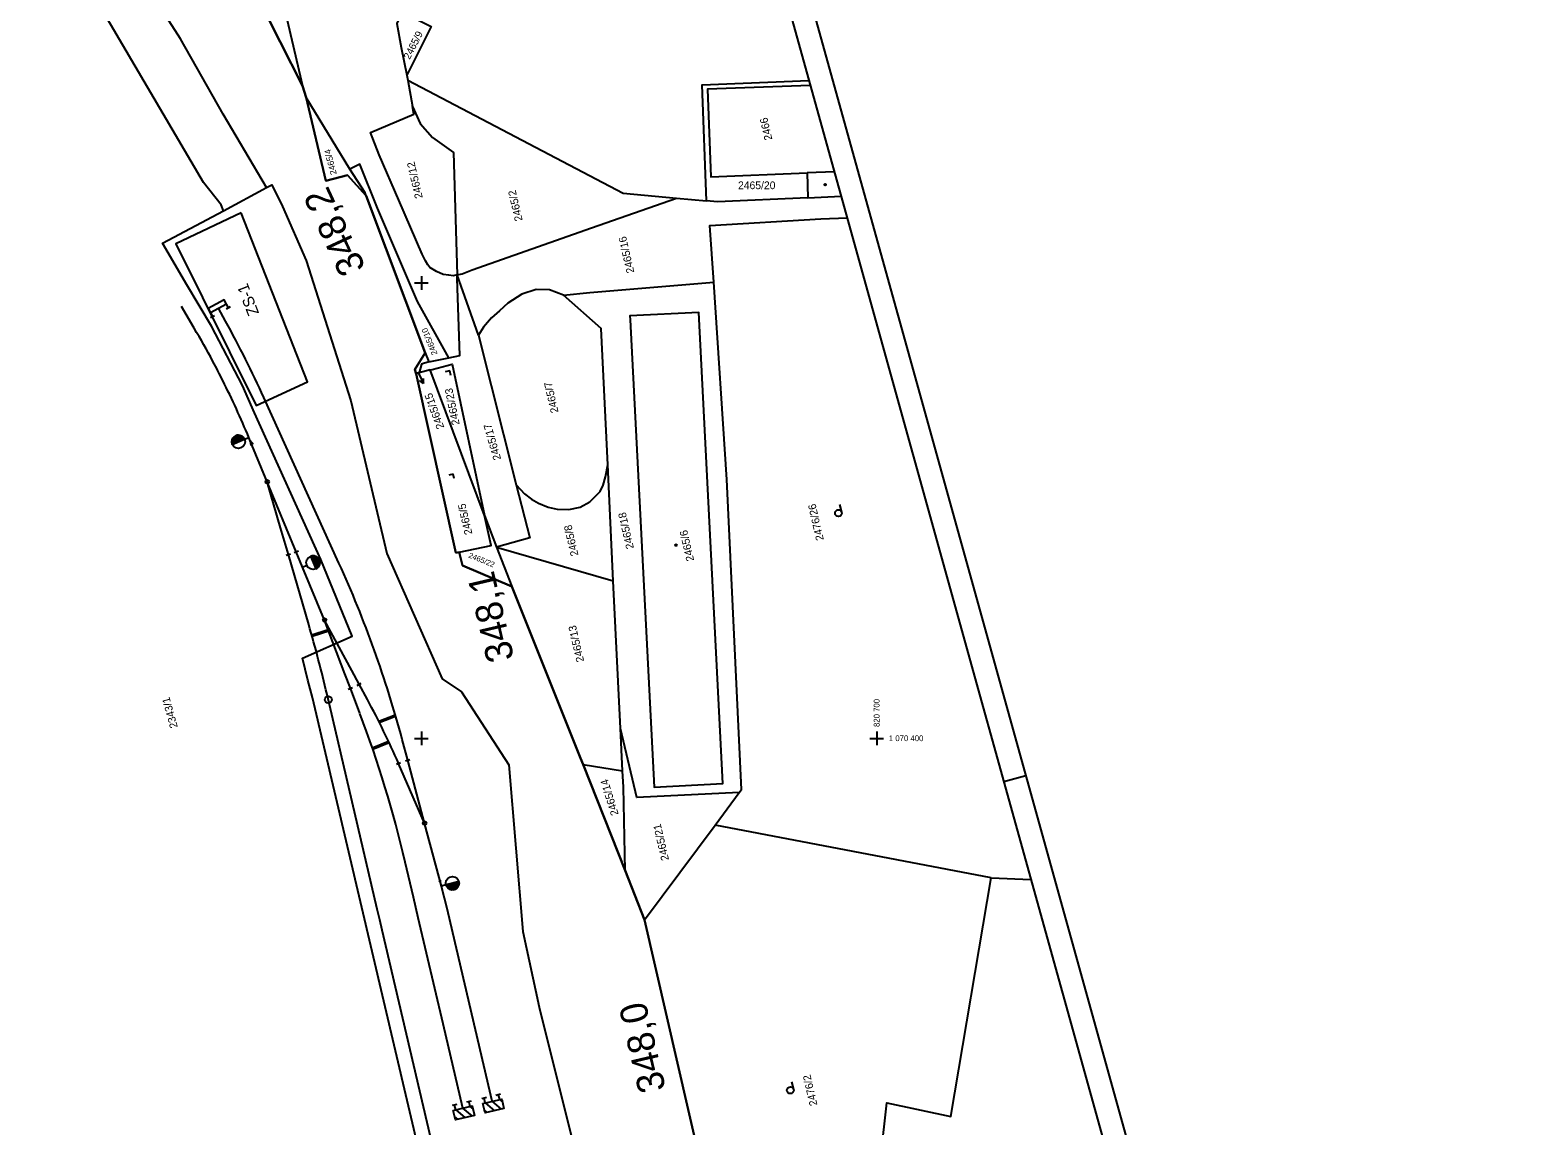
# Model space of a CAD drawing. Extents: x -821122 to -820555, y -1070892 to -1069801.
# Drawn here: x -820885.9 to -820554.8, y -1070485 to -1070244.5 of the extents above; entities that cross this region are included whole.
import ezdxf

# ---------------------------------------------------------------- set-up
doc = ezdxf.new("R2010")
doc.units = 0
for name, color, linetype in [('Hranice drážního pozemku', 7, 'Continuous'), ('Hranice parcel', 7, 'Continuous'), ('Katastrální hranice', 7, 'Continuous'), ('Osa staničení koleje', 7, 'Continuous'), ('Parcelní čísla', 7, 'Continuous'), ('Pop  PČ popisy', 7, 'Continuous'), ('Ram', 7, 'Continuous'), ('Sttaniceni a namezniky', 7, 'Continuous'), ('Vnitřní kresba', 7, 'Continuous'), ('Vrstva 61', 7, 'Continuous'), ('Vrstva 63', 7, 'Continuous'), ('Značky budov', 7, 'Continuous'), ('Značky kultur', 7, 'Continuous')]:
    doc.layers.add(name, color=color, linetype=linetype)

msp = doc.modelspace()

# ---------------------------------------------------------------- linework, layer by layer
at = {"layer": 'Hranice drážního pozemku'}
for p, q in [((-820835.88, -1070237.32), (-820826.1, -1070256.7)), ((-820826.1, -1070256.7), (-820825.3, -1070259.25)), ((-820812.1, -1070280.9), (-820812.1, -1070280.9)), ((-820812.1, -1070280.9), (-820799.14, -1070315.36)), ((-820801.15, -1070319.91), (-820792.39, -1070359.23)), ((-820792.39, -1070359.23), (-820791.67, -1070359.08)), ((-820780.16, -1070366.62), (-820765.05, -1070404.29)), ((-820765.05, -1070404.29), (-820764.48, -1070405.73)), ((-820764.48, -1070405.73), (-820755.27, -1070429)), ((-820755.27, -1070429), (-820751, -1070439.83)), ((-820751, -1070439.83), (-820721.42, -1070568.42))]:
    msp.add_line(p, q, dxfattribs=at)
for points in [[(-820825.3, -1070259.25), (-820821, -1070277.6), (-820816.2, -1070276.3), (-820812.1, -1070280.9)], [(-820799.14, -1070315.36), (-820801.45, -1070319), (-820801.15, -1070319.91)], [(-820791.67, -1070359.08), (-820790.95, -1070362.05), (-820780.16, -1070366.62)]]:
    msp.add_lwpolyline(points, dxfattribs=at)
at = {"layer": 'Hranice parcel'}
for p, q in [((-820803.2, -1070254.4), (-820803, -1070255.5)), ((-820803, -1070255.5), (-820801.94, -1070261.25)), ((-820815.71, -1070274.99), (-820825.3, -1070259.25)), ((-820744, -1070281.37), (-820737.36, -1070281.98)), ((-820787.47, -1070311.48), (-820792.13, -1070298.22)), ((-820787.47, -1070311.48), (-820779.15, -1070344.32)), ((-820799.14, -1070315.36), (-820798.35, -1070317.32)), ((-820798.35, -1070317.32), (-820793.99, -1070316.42)), ((-820800.46, -1070319.73), (-820801.15, -1070319.91)), ((-820798.04, -1070319.1), (-820800.46, -1070319.73)), ((-820786.11, -1070351.02), (-820798.04, -1070319.1)), ((-820757.86, -1070365.37), (-820759.03, -1070339.93)), ((-820786.11, -1070351.02), (-820783.5, -1070358)), ((-820783.5, -1070358), (-820757.86, -1070365.37)), ((-820783.5, -1070358), (-820780.16, -1070366.62)), ((-820756.26, -1070397.81), (-820757.86, -1070365.37)), ((-820755.8, -1070407.09), (-820756.26, -1070397.81)), ((-820764.48, -1070405.73), (-820755.8, -1070407.09)), ((-820735.51, -1070419.02), (-820730.21, -1070411.89)), ((-820751, -1070439.83), (-820735.51, -1070419.02)), ((-820674.9, -1070430.61), (-820735.51, -1070419.02)), ((-820674.9, -1070430.61), (-820666.15, -1070430.93))]:
    msp.add_line(p, q, dxfattribs=at)
for points in [[(-820830.93, -1070230.58), (-820830.77, -1070236.59), (-820826.1, -1070256.7)], [(-820804.2, -1070240.46), (-820805.38, -1070243.04), (-820804.45, -1070248.28), (-820803.2, -1070254.4)], [(-820804.2, -1070240.46), (-820797.83, -1070243.67), (-820803.2, -1070254.4)], [(-820803, -1070255.5), (-820755.71, -1070280.3), (-820744, -1070281.37)], [(-820737.36, -1070281.98), (-820738.31, -1070256.5), (-820714.88, -1070255.56)], [(-820714.59, -1070256.61), (-820737.16, -1070257.48), (-820736.4, -1070276.66), (-820715.25, -1070275.85), (-820715.14, -1070281.29)], [(-820792.13, -1070298.22), (-820793, -1070298.4), (-820793.95, -1070298.3), (-820795.2, -1070298.1), (-820796.7, -1070297.5), (-820798.1, -1070296.6), (-820798.6, -1070296), (-820799.1, -1070295.1), (-820799.82, -1070293.66), (-820804.97, -1070281.8), (-820809.25, -1070271.85), (-820811.2, -1070266.98), (-820801.63, -1070262.92), (-820801.94, -1070261.25)], [(-820801.94, -1070261.25), (-820800.23, -1070264.95), (-820797.52, -1070268.04), (-820792.96, -1070271.33), (-820792.13, -1070298.22)], [(-820793.99, -1070316.42), (-820800.87, -1070304.08), (-820809.66, -1070283.54), (-820813.53, -1070273.91), (-820815.71, -1070274.99)], [(-820812.1, -1070280.9), (-820812.3, -1070280.2), (-820815.71, -1070274.99)], [(-820792.13, -1070298.22), (-820791, -1070298), (-820788.84, -1070297.13), (-820762.63, -1070287.92), (-820744, -1070281.37)], [(-820715.14, -1070281.29), (-820735, -1070282.2), (-820737.36, -1070281.98)], [(-820715.14, -1070281.29), (-820707.82, -1070280.96)], [(-820735.8, -1070299.79), (-820736.63, -1070287.37), (-820712.28, -1070285.91), (-820706.49, -1070285.73)], [(-820793.99, -1070316.42), (-820791.57, -1070315.92), (-820792.1, -1070299.04), (-820792.13, -1070298.22)], [(-820768.79, -1070302.68), (-820771.86, -1070301.49), (-820774.82, -1070301.43), (-820777.93, -1070302.46), (-820780.99, -1070304.44), (-820782.84, -1070306.1), (-820784.56, -1070307.68), (-820786.32, -1070309.72), (-820787.47, -1070311.48)], [(-820768.79, -1070302.68), (-820763, -1070302.1), (-820735.8, -1070299.79)], [(-820730.21, -1070411.89), (-820729.73, -1070411.24), (-820732.91, -1070343.18), (-820735.8, -1070299.79)], [(-820759.03, -1070339.93), (-820760.52, -1070309.99), (-820768.79, -1070302.68)], [(-820754.18, -1070308.11), (-820748.91, -1070410.67), (-820733.78, -1070409.91), (-820739.09, -1070306.45), (-820754.22, -1070307.24), (-820754.18, -1070308.11)], [(-820798.35, -1070317.32), (-820799.93, -1070317.83), (-820800.46, -1070319.73)], [(-820798.04, -1070319.1), (-820797.62, -1070318.99), (-820793.2, -1070317.84), (-820786.11, -1070351.02)], [(-820779.15, -1070344.32), (-820777.33, -1070346.31), (-820775.83, -1070347.45), (-820774.3, -1070348.31), (-820772.13, -1070349.23), (-820770.14, -1070349.67), (-820767.58, -1070349.73), (-820765.16, -1070349.21), (-820762.99, -1070348.02), (-820760.75, -1070345.78), (-820760.09, -1070344.39), (-820759.57, -1070342.58), (-820759.03, -1070339.93)], [(-820779.15, -1070344.32), (-820776.21, -1070355.93), (-820783.5, -1070358)], [(-820791.67, -1070359.08), (-820784.69, -1070357.66), (-820786.11, -1070351.02)], [(-820730.21, -1070411.89), (-820752.71, -1070412.96), (-820756.26, -1070397.81)], [(-820755.27, -1070429), (-820755.62, -1070410.67), (-820755.8, -1070407.09)], [(-820707.79, -1070569.63), (-820697.8, -1070480), (-820683.7, -1070483), (-820674.9, -1070430.61)]]:
    msp.add_lwpolyline(points, dxfattribs=at)
at = {"layer": 'Katastrální hranice'}
for p, q in [((-820826.1, -1070256.7), (-820835.88, -1070237.32)), ((-820825.3, -1070259.25), (-820826.1, -1070256.7)), ((-820799.14, -1070315.36), (-820812.1, -1070280.9)), ((-820792.39, -1070359.23), (-820801.15, -1070319.91)), ((-820791.67, -1070359.08), (-820792.39, -1070359.23)), ((-820765.05, -1070404.29), (-820780.16, -1070366.62)), ((-820764.48, -1070405.73), (-820765.05, -1070404.29)), ((-820755.27, -1070429), (-820764.48, -1070405.73)), ((-820751, -1070439.83), (-820755.27, -1070429)), ((-820721.42, -1070568.42), (-820751, -1070439.83))]:
    msp.add_line(p, q, dxfattribs=at)
for points in [[(-820812.1, -1070280.9), (-820816.2, -1070276.3), (-820821, -1070277.6), (-820825.3, -1070259.25)], [(-820801.15, -1070319.91), (-820801.45, -1070319), (-820799.14, -1070315.36)], [(-820780.16, -1070366.62), (-820790.95, -1070362.05), (-820791.67, -1070359.08)]]:
    msp.add_lwpolyline(points, dxfattribs=at)
at = {"layer": 'Osa staničení koleje'}
for p, q in [((-820849.87, -1070309.94), (-820852.68, -1070305.19)), ((-820846.32, -1070306.47), (-820842.81, -1070304.55)), ((-820842.77, -1070305.67), (-820841.89, -1070305.19)), ((-820846.27, -1070307.59), (-820845.4, -1070307.11)), ((-820842.98, -1070308.41), (-820844.56, -1070305.51)), ((-820818.09, -1070361.48), (-820834.6, -1070325.15)), ((-820840.68, -1070335.1), (-820841.61, -1070334.71)), ((-820841.17, -1070335.3), (-820841.61, -1070335.12)), ((-820841.52, -1070335.44), (-820838.81, -1070334.32)), ((-820840.19, -1070334.89), (-820841.52, -1070334.34)), ((-820839.7, -1070334.69), (-820841.34, -1070334.01)), ((-820839.21, -1070334.49), (-820841.05, -1070333.72)), ((-820838.86, -1070334.22), (-820840.62, -1070333.5)), ((-820838.81, -1070334.32), (-820837.86, -1070333.93)), ((-820837.56, -1070334.67), (-820837.86, -1070333.93)), ((-820829.68, -1070359.74), (-820828.72, -1070359.46)), ((-820824.73, -1070374.99), (-820829.2, -1070359.6)), ((-820827.92, -1070359.18), (-820827, -1070358.8)), ((-820826.07, -1070362.36), (-820827.46, -1070358.99)), ((-820824.33, -1070360.01), (-820823.18, -1070362.78)), ((-820822.29, -1070361.12), (-820824.2, -1070360.33)), ((-820822.49, -1070360.61), (-820824.1, -1070359.94)), ((-820822.27, -1070361.56), (-820823.98, -1070360.85)), ((-820822.37, -1070361.95), (-820823.77, -1070361.37)), ((-820826.07, -1070362.36), (-820825.14, -1070361.97)), ((-820822.57, -1070362.3), (-820823.55, -1070361.9)), ((-820822.88, -1070362.61), (-820823.33, -1070362.42)), ((-820824.08, -1070377.26), (-820820.45, -1070376.07)), ((-820824, -1070377.55), (-820820.35, -1070376.35)), ((-820814.09, -1070388.34), (-820813.2, -1070387.86)), ((-820811.82, -1070391.48), (-820813.65, -1070388.1)), ((-820816.04, -1070389.16), (-820815.11, -1070388.8)), ((-820813.49, -1070394.48), (-820815.58, -1070388.98)), ((-820809.37, -1070396.2), (-820805.73, -1070394.78)), ((-820809.24, -1070396.47), (-820805.65, -1070395.07)), ((-820810.77, -1070402.05), (-820807.22, -1070400.62)), ((-820810.67, -1070402.34), (-820807.09, -1070400.89)), ((-820802.99, -1070404.76), (-820804.2, -1070400.24)), ((-820803.47, -1070404.89), (-820802.51, -1070404.63)), ((-820805.48, -1070405.67), (-820804.56, -1070405.26)), ((-820799.29, -1070418.58), (-820805.02, -1070405.47)), ((-820794.59, -1070432.15), (-820795.59, -1070432.4)), ((-820791.76, -1070431.41), (-820794.59, -1070432.15)), ((-820794.55, -1070432.25), (-820792.92, -1070433.21)), ((-820794.18, -1070432.04), (-820792.46, -1070433.05)), ((-820793.67, -1070431.9), (-820792.14, -1070432.8)), ((-820793.15, -1070431.77), (-820791.91, -1070432.5)), ((-820792.64, -1070431.64), (-820791.76, -1070432.15)), ((-820792.12, -1070431.5), (-820791.71, -1070431.75)), ((-820792.19, -1070480.37), (-820793.23, -1070480.61)), ((-820792.46, -1070481.53), (-820792.71, -1070480.49)), ((-820789.07, -1070479.64), (-820790.11, -1070479.88)), ((-820789.59, -1070479.76), (-820789.35, -1070480.8)), ((-820789.35, -1070480.8), (-820788.68, -1070481.3)), ((-820785.71, -1070478.85), (-820786.75, -1070479.1)), ((-820785.99, -1070480.01), (-820786.23, -1070478.98)), ((-820785.99, -1070480.01), (-820783.94, -1070481.73)), ((-820782.39, -1070481.36), (-820784.43, -1070479.65)), ((-820782.6, -1070478.12), (-820783.64, -1070478.37)), ((-820783.12, -1070478.25), (-820782.87, -1070479.28)), ((-820782.87, -1070479.28), (-820782.21, -1070479.79)), ((-820791.98, -1070483.61), (-820792.64, -1070483.1)), ((-820792.46, -1070481.53), (-820790.42, -1070483.24)), ((-820788.86, -1070482.88), (-820790.91, -1070481.17)), ((-820785.5, -1070482.09), (-820786.17, -1070481.59))]:
    msp.add_line(p, q, dxfattribs=at)
for points in [[(-820842.33, -1070305.43), (-820843.29, -1070303.67), (-820846.8, -1070305.6), (-820845.84, -1070307.35)], [(-820827.46, -1070358.99), (-820833.83, -1070343.65), (-820837.56, -1070334.67)], [(-820836.95, -1070335.46), (-820837.56, -1070334.67), (-820837.43, -1070335.66)], [(-820829.2, -1070359.6), (-820830.9, -1070353.75), (-820833.83, -1070343.65)], [(-820815.58, -1070388.98), (-820816.78, -1070385.8), (-820821.23, -1070374), (-820826.07, -1070362.36)], [(-820813.65, -1070388.1), (-820815.26, -1070385.11), (-820821.23, -1070374)], [(-820761.02, -1070645.41), (-820786.89, -1070534.87), (-820787.46, -1070532.43), (-820788.03, -1070530), (-820808.6, -1070442.09), (-820809.13, -1070439.8), (-820809.67, -1070437.51), (-820820.71, -1070390.32)], [(-820795.59, -1070432.4), (-820799.29, -1070418.58), (-820802.99, -1070404.76)], [(-820790.91, -1070481.17), (-820795.24, -1070462.63), (-820800.68, -1070439.41), (-820801.22, -1070437.11), (-820801.75, -1070434.81), (-820803.55, -1070427.14)], [(-820796.05, -1070431.19), (-820795.8, -1070431.62), (-820795.8, -1070431.12)], [(-820784.43, -1070479.65), (-820794.12, -1070438.25), (-820794.33, -1070437.36), (-820794.89, -1070435.08), (-820795.48, -1070432.8), (-820795.59, -1070432.4)], [(-820792.98, -1070481.65), (-820788.83, -1070480.68), (-820788.34, -1070482.76), (-820792.5, -1070483.73), (-820792.98, -1070481.65)], [(-820786.51, -1070480.14), (-820782.35, -1070479.16), (-820781.87, -1070481.24), (-820786.02, -1070482.21), (-820786.51, -1070480.14)]]:
    msp.add_lwpolyline(points, dxfattribs=at)
for centre, radius in [((-820840.17, -1070334.88), 1.46), ((-820833.83, -1070343.65), 0.4), ((-820823.76, -1070361.4), 1.5), ((-820821.23, -1070374), 0.4), ((-820799.29, -1070418.58), 0.4), ((-820793.17, -1070431.78), 1.46)]:
    msp.add_circle(centre, radius, dxfattribs=at)
for centre, radius, start, end in [((-821022.08, -1070411.64), 200, 28.1669, 30.5657), ((-820840.17, -1070334.88), 1.46, 22.5565, 202.5173), ((-820823.76, -1070361.4), 1.5, 292.5346, 112.5346), ((-820793.17, -1070431.78), 1.46, 194.5518, 14.5127)]:
    msp.add_arc(centre, radius, start, end, dxfattribs=at)
for centre, major_axis, ratio, start_param, end_param in [((-821062.2, -1070428.57), (-187.85, 164.97), 0.999981, 4.288762, 4.363646), ((-821021.4, -1070410.78), (-93.91, 176.58), 0.995018, 4.689459, 4.713006), ((-821022.45, -1070410.92), (0, 200), 0.999983, 5.107568, 5.176383), ((-821045.68, -1070464.9), (-139.53, 207.44), 0.999954, 4.381904, 4.546806), ((-821102.72, -1070456.2), (-73.52, 290.85), 0.96534, 4.694931, 4.747744), ((-821056.7, -1070486.4), (38.3, 257.16), 0.999985, 5.090175, 5.221577), ((-820979.11, -1070481.53), (-110.75, 154.39), 0.9999, 4.502101, 4.583959)]:
    msp.add_ellipse(centre, major_axis=major_axis, ratio=ratio, start_param=start_param, end_param=end_param, dxfattribs=at)
at = {"layer": 'Pop  PČ popisy'}
for p, q in [((-820800.8, -1070319.48), (-820799.54, -1070322.07)), ((-820799.54, -1070322.07), (-820800.39, -1070321.42)), ((-820799.54, -1070322.07), (-820799.53, -1070321))]:
    msp.add_line(p, q, dxfattribs=at)
at = {"layer": 'Ram'}
msp.add_line((-820667.28, -1070408.2), (-820672.09, -1070409.53), dxfattribs=at)
for points in [[(-820835.94, -1069801.19), (-820554.83, -1070812.86)], [(-820839.42, -1069807.35), (-820560.99, -1070809.39)]]:
    msp.add_lwpolyline(points, dxfattribs=at)
at = {"layer": 'Sttaniceni a namezniky'}
msp.add_circle((-820820.44, -1070391.49), 0.75, dxfattribs=at)
at = {"layer": 'Vnitřní kresba'}
msp.add_line((-820709.3, -1070275.62), (-820715.25, -1070275.85), dxfattribs=at)
at = {"layer": 'Vrstva 61'}
for p, q in [((-820800, -1070298.5), (-820800, -1070301.5)), ((-820801.5, -1070300), (-820798.5, -1070300)), ((-820801.5, -1070400), (-820798.5, -1070400)), ((-820800, -1070398.5), (-820800, -1070401.5)), ((-820701.5, -1070400), (-820698.5, -1070400)), ((-820700, -1070398.5), (-820700, -1070401.5))]:
    msp.add_line(p, q, dxfattribs=at)
at = {"layer": 'Vrstva 63'}
for points in [[(-820843.48, -1070284.13), (-820843.93, -1070282.84), (-820847.81, -1070277.93), (-820871.73, -1070237.25), (-820885.29, -1070218.2), (-820887.54, -1070214.67), (-820897.96, -1070197.77), (-820903.32, -1070188.38), (-820912.12, -1070190.61), (-820919.97, -1070176.29), (-820926.49, -1070162.4), (-820934.28, -1070147.4), (-820935.96, -1070145.11), (-820960.28, -1070123.34), (-820989.85, -1070096.95), (-820989.01, -1070086.94)], [(-820833.99, -1070279.04), (-820843.49, -1070262.96), (-820852.87, -1070246.42), (-820862.31, -1070231.6), (-820865.19, -1070221.48), (-820871.51, -1070211.52), (-820874.37, -1070206.78), (-820882.74, -1070199.34)], [(-820782.06, -1070569.19), (-820823.93, -1070391.03), (-820824.95, -1070387.21), (-820826.08, -1070382.39), (-820815.22, -1070377.53), (-820822.07, -1070360.7), (-820836.66, -1070328.48), (-820839.3, -1070322.5), (-820846.11, -1070309.46), (-820851.46, -1070300.37), (-820856.81, -1070291.29), (-820843.48, -1070284.13), (-820833.99, -1070279.04), (-820832.86, -1070278.43), (-820830.46, -1070283.22), (-820825.29, -1070295.05), (-820815.49, -1070325.84), (-820807.6, -1070359.39), (-820795.41, -1070386.91), (-820791.18, -1070389.77), (-820780.82, -1070405.78), (-820777.68, -1070442.39), (-820774.11, -1070459), (-820761.04, -1070511.47)]]:
    msp.add_lwpolyline(points, dxfattribs=at)
msp.add_lwpolyline([(-820839.58, -1070284.56), (-820853.94, -1070291.42), (-820836.24, -1070326.89), (-820825.03, -1070321.71)], close=True, dxfattribs=at)
at = {"layer": 'Značky budov'}
for centre in [(-820711.33, -1070278.39), (-820744.07, -1070357.55)]:
    msp.add_circle(centre, 0.175, dxfattribs=at)
at = {"layer": 'Značky kultur'}
for p, q in [((-820793.77, -1070319.3), (-820794.74, -1070319.53)), ((-820793.54, -1070320.28), (-820793.77, -1070319.3)), ((-820793.02, -1070341.96), (-820794, -1070342.19)), ((-820792.8, -1070342.94), (-820793.02, -1070341.96)), ((-820707.68, -1070350.35), (-820708.07, -1070348.65)), ((-820718.24, -1070477.06), (-820718.64, -1070475.36))]:
    msp.add_line(p, q, dxfattribs=at)
for centre in [(-820708.41, -1070350.52), (-820718.97, -1070477.23)]:
    msp.add_circle(centre, 0.75, dxfattribs=at)

# ---------------------------------------------------------------- texts
at = {"layer": 'Parcelní čísla'}
for s, height, rotation, p in [('2465/9', 1.6, 63, (-820802.56, -1070251.05)), ('2466', 1.7, 103, (-820722.92, -1070268.46)), ('2465/4', 1.4, 104.5515, (-820818.56, -1070276.05)), ('2465/12', 1.7, 103, (-820799.68, -1070281.26)), ('2465/2', 1.7, 103, (-820777.75, -1070286.23)), ('2465/16', 1.7, 103, (-820753.22, -1070297.64)), ('2465/10', 1.3, 112, (-820796.43, -1070315.54)), ('2465/15', 1.7, 109.932, (-820794.94, -1070331.71)), ('2465/23', 1.7, 101.3797, (-820791.58, -1070331.02)), ('2465/7', 1.7, 103, (-820769.86, -1070328.35)), ('2465/17', 1.7, 106, (-820782.47, -1070338.64)), ('2465/5', 1.7, 103, (-820788.78, -1070355.06)), ('2465/18', 1.7, 103, (-820753.31, -1070358.21)), ('2476/26', 1.7, 103, (-820711.61, -1070356.36)), ('2465/8', 1.7, 103, (-820765.49, -1070359.75)), ('2465/6', 1.7, 103, (-820740.09, -1070360.89)), ('2465/22', 1.2, 338, (-820789.75, -1070360.23)), ('2465/13', 1.7, 103, (-820764.24, -1070383.03)), ('2343/1', 1.7, 105.5289, (-820853.47, -1070397.48)), ('2465/14', 1.7, 107.1532, (-820756.66, -1070416.64)), ('2465/21', 1.7, 103, (-820745.61, -1070426.62)), ('2476/2', 1.7, 103, (-820713.02, -1070480.46))]:
    msp.add_text(s, height=height, rotation=rotation, dxfattribs=at).set_placement(p)
msp.add_text('2465/20', height=1.7, dxfattribs=at).set_placement((-820730.46, -1070279.4))
at = {"layer": 'Sttaniceni a namezniky'}
for s, rotation, p in [('348,2', 114.979, (-820812.13, -1070296.65)), ('348,1', 103.1701, (-820779.58, -1070382.47)), ('348,0', 103.1705, (-820746.27, -1070477))]:
    msp.add_text(s, height=6, rotation=rotation, dxfattribs=at).set_placement(p)
at = {"layer": 'Vrstva 61'}
msp.add_text('820 700', height=1.275, rotation=90, dxfattribs=at).set_placement((-820699.39, -1070397.48))
msp.add_text('1 070 400', height=1.275, dxfattribs=at).set_placement((-820697.34, -1070400.59))
at = {"layer": 'Vrstva 63'}
msp.add_text('ZS-1', height=2.5, rotation=111.2148, dxfattribs=at).set_placement((-820835.59, -1070306.62))

doc.saveas('drawing.dxf')
